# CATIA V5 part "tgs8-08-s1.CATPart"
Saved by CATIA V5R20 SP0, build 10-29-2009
Part number: TGS8-08-S1
Revision: 1
Definition: design
Nomenclature: TGS8-08-S1
Source: made
Description: NOT SPECIFIED
Bounding box of the stored display mesh (mm): x -3 to 3, y -8 to 0, z -22 to 0.6
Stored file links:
  C:\Users\Raffaele\Desktop\3D X SITO CF\I-MOLD\TGS-S1\tgs8-s1.step\tgs8-08-s1.CATPart
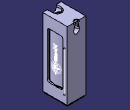
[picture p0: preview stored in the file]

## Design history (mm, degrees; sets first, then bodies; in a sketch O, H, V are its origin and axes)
Set1
  DatumCurve1 "COMPOSITE_CURVE #4115"
  DatumCurve2 "COMPOSITE_CURVE #4161"
  DatumCurve3 "COMPOSITE_CURVE #4394"
  DatumCurve4 "COMPOSITE_CURVE #4454"
  DatumCurve5 "COMPOSITE_CURVE #4511"
  DatumCurve6 "COMPOSITE_CURVE #4672"
  DatumCurve7 "COMPOSITE_CURVE #4699"
  DatumCurve8 "COMPOSITE_CURVE #4726"
  DatumCurve9 "COMPOSITE_CURVE #4809"
  DatumCurve10 "COMPOSITE_CURVE #4860"
  Line1 "LINE #4864": stored without definition
  DatumSurface1 "OPEN_SHELL #3967"
  DatumSurface2 "OPEN_SHELL #4064"
Body1 "MANIFOLD_SOLID_BREP #4065" (main body)
  Solid1: solid without history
